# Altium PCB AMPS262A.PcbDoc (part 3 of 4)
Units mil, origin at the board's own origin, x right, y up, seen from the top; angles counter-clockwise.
Board outline 5314.96 x 4803.15 mil, 4 copper layers (Top Layer, GND, Copper Layer 3, Bottom Layer), stack 79.28 mil thick; 324 components, 156 nets, 943 pads, 1411 vias.
Unrouted connection lines stored in the file: 130.
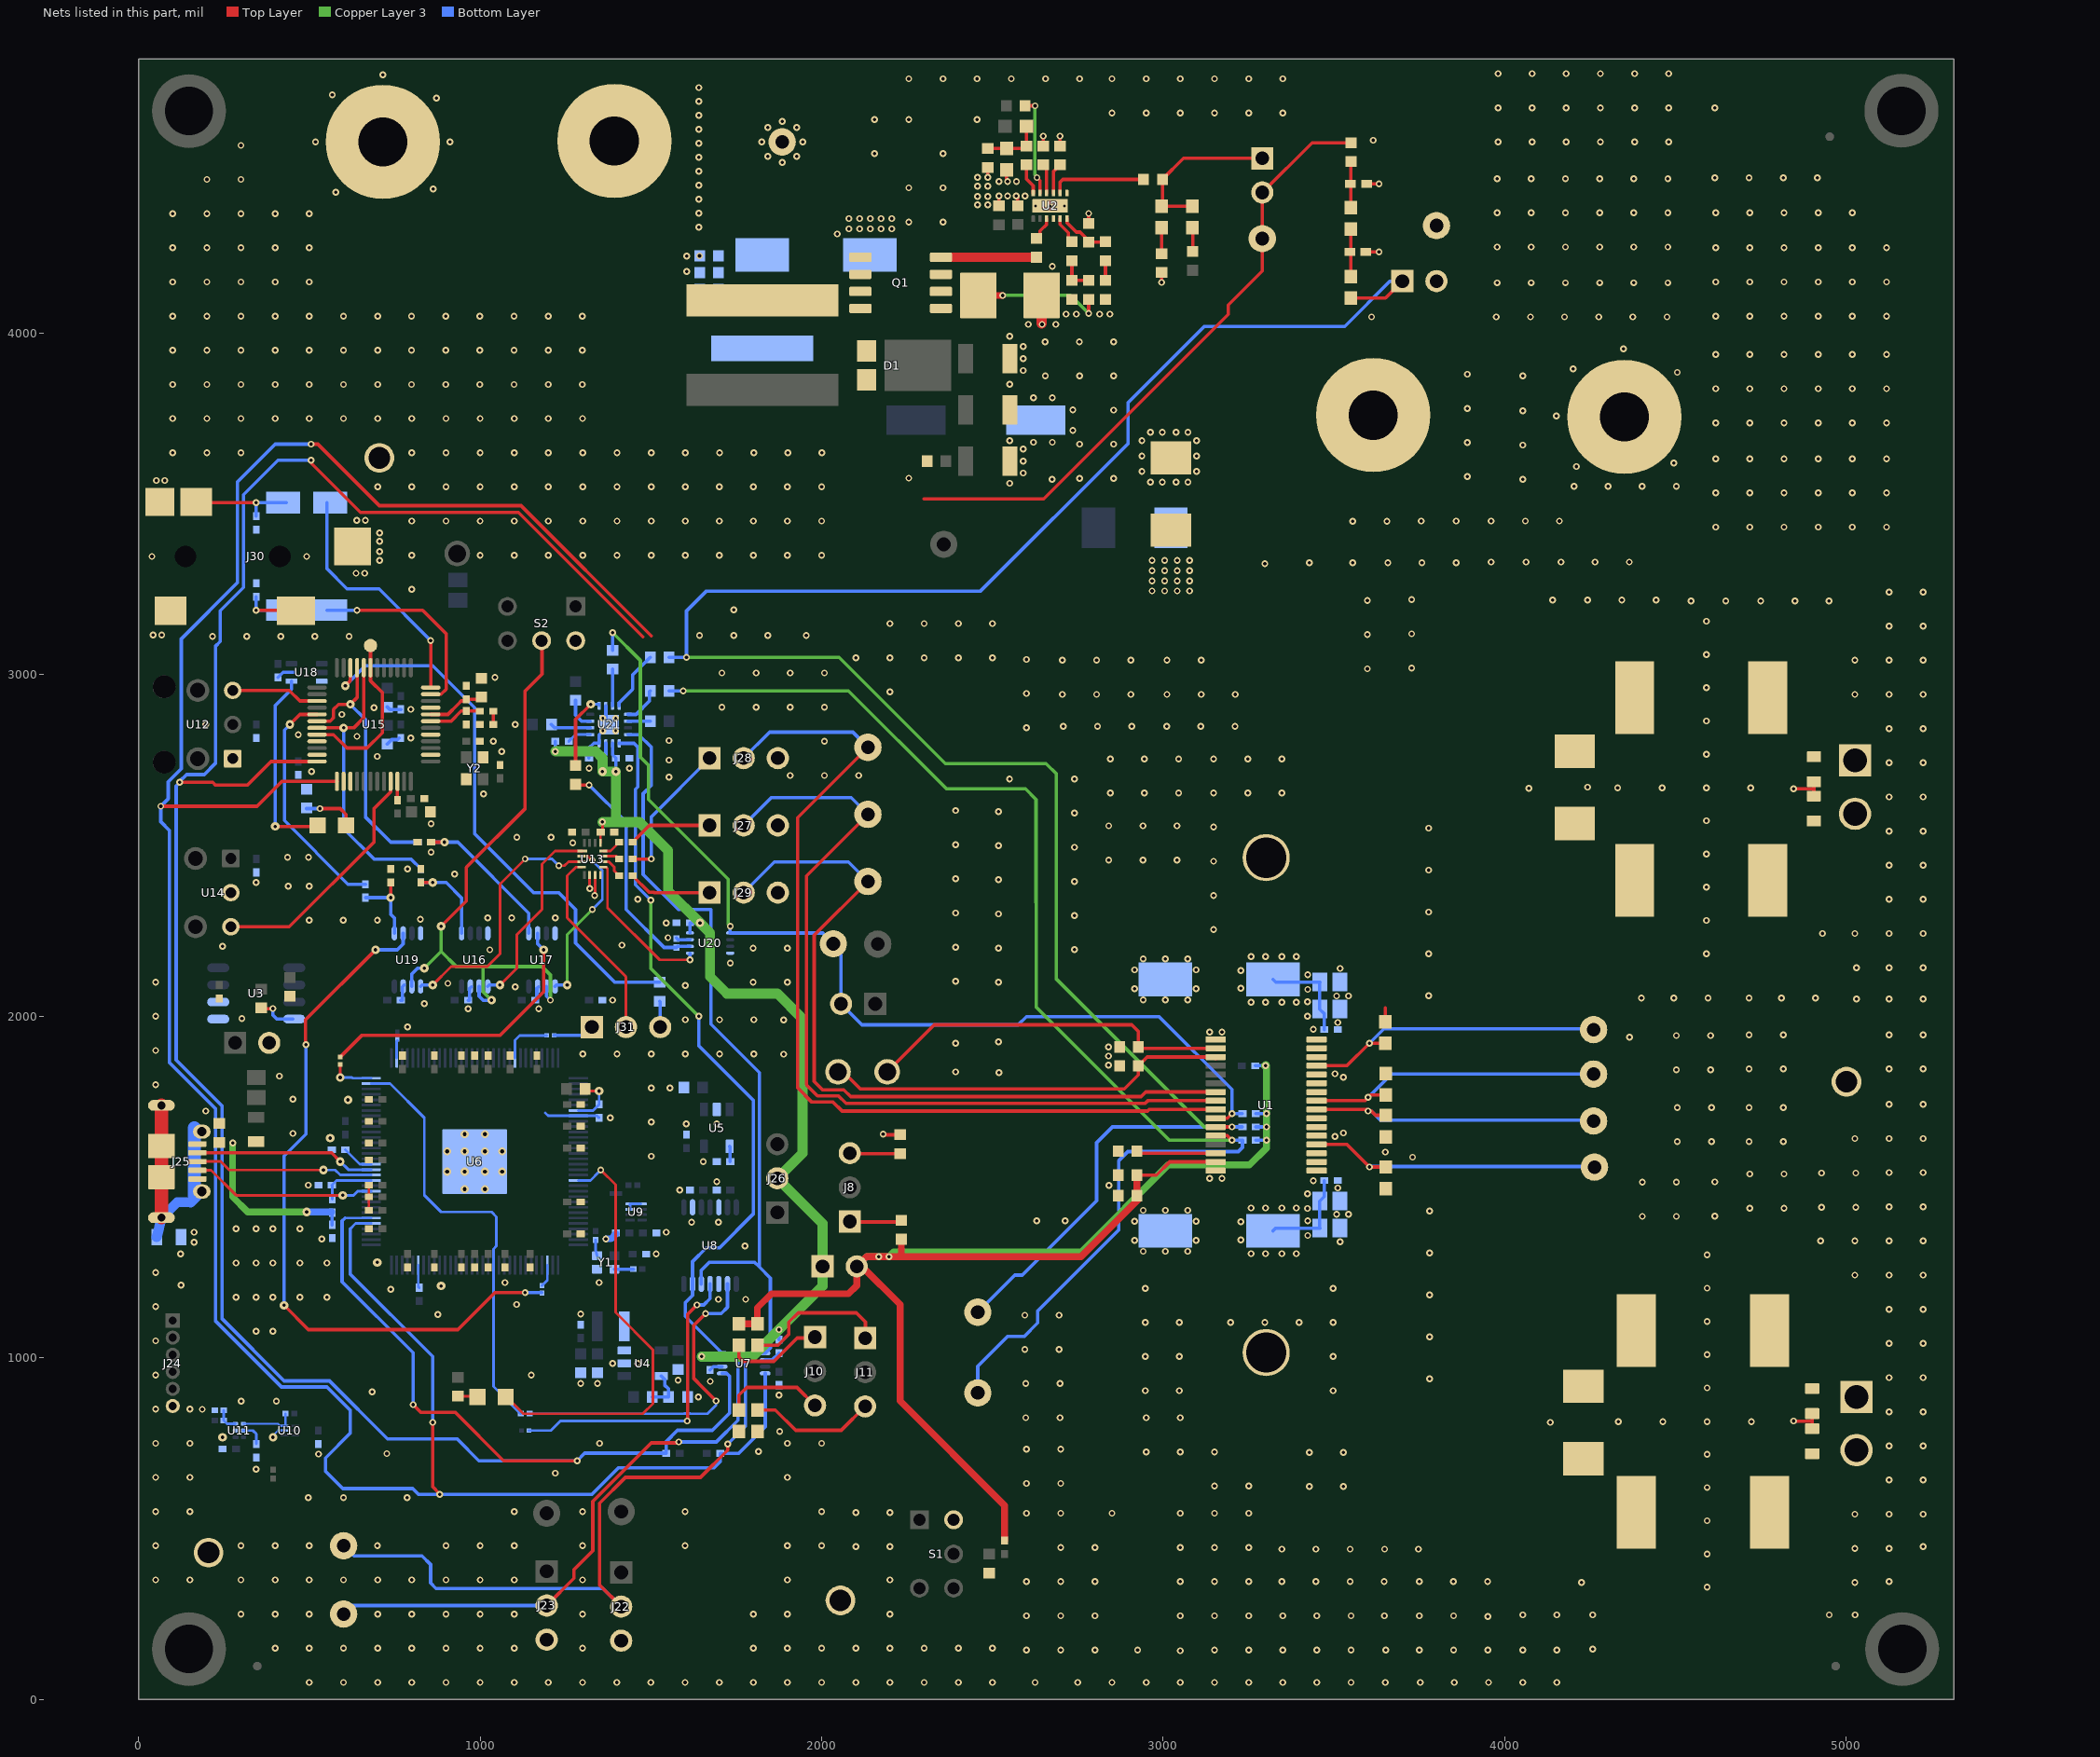
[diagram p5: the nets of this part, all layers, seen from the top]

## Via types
v1: diameter 20, hole 10, Top Layer to Bottom Layer, tented both sides, 1299 vias
v2: diameter 25, hole 10, Top Layer to Bottom Layer, tented both sides, 87 vias
v3: diameter 23.62, hole 11.81, Top Layer to Bottom Layer, 12 vias
v4: diameter 19.68, hole 7.87, Top Layer to Bottom Layer, 7 vias
v5: diameter 20, hole 10, Top Layer to Bottom Layer, 6 vias

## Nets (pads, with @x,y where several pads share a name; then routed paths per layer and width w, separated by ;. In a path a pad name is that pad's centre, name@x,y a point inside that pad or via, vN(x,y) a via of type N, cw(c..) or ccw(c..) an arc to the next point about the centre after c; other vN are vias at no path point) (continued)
BST_A+: C14.1 TP21.1 U1.20 | length 889.5
  Top Layer w9.84: U1.20@3449,1624.97 3537.89,1624.97 v1(3603.86,1559) C14.1@3651.25,1559
  Bottom Layer w10: v1(3603.86,1559) 3605.14,1560.28 4260.75,1560.28 TP21.1@4262.5,1558.52
BST_A-: C16.1 TP22.1 U1.24 | length 881.3
  Top Layer w9.84: 3621.5,1710.36 C16.1@3651.28,1710.36
  Top Layer w10: U1.24@3449,1727.33 3595.17,1727.33 v1(3600,1722.5) 3609.36,1722.5 3621.5,1710.36
  Bottom Layer w10: v1@3600,1722.36 3609.5,1722.36 3635.89,1695.97 4257.56,1695.97 TP22.1@4260,1693.52
BST_B+: C18.1 TP23.1 U1.29 | length 897.2
  Top Layer w9.84: U1.29@3449,1855.29 3537.89,1855.29 v1(3603.61,1921) C18.1@3650,1921
  Bottom Layer w10: v1(3603.61,1921) 3645.97,1963.37 TP23.1@4255,1963.37
BST_B-: C20.1 TP24.1 U1.25 | length 897.7
  Top Layer w10: U1.25@3449,1752.92 3590.42,1752.92 v1(3600,1762.5) 3607.4,1769.9 C20.1@3651.28,1769.9
  Bottom Layer w10: v1(3600,1762.5) 3668.52,1831.02 TP24.1@4260,1831.02
COMP: C38.1 C39.1 U2.6 | length 150.1
  Top Layer w9.84: U2.6@2717.77,4335.49 2717.77,4324.13 2745.78,4296.12 2756.76,4296.12 2781.75,4271.14 C38.1@2781.75,4266.6 C39.1@2829.97,4266.6
CS: R17.1 U2.5 | length 82.2
  Top Layer w9.84: U2.5@2698.08,4335.49 2698.08,4318.76 2722.69,4294.16 2722.69,4277.42 R17.1@2732.53,4267.58
DOUT-XMOS: R47.2 U19.2 | length 2100
  Top Layer w9.84: v2(426,1154) 497.32,1082.68 935.04,1082.68 1043.31,1190.94 v1(1131.89,1190.94) ; v1(490,1917.5) 489.11,1918.39 489.11,1990.09 v2(693.9,2194.88)
  Bottom Layer w9.84: v2(426,1154) 426,1591 490,1655 v1(490,1917.5) ; v2(693.9,2194.88) 757.87,2194.88 774.61,2211.61 U19.2@774.61,2243.11 ; v1(1131.89,1190.94) R47.2@1179.92,1190.94
DVDD1: C11.2 C12.1 J3.2 R1.2 R2.2 R3.2 R4.2 R5.2 R7.2 R8.2 R9.2 U1.15 | length 4439.1
  Top Layer w10: C12.1@2923.28,1535 2980.17,1535 3018.96,1573.79 U1.15@3153.72,1573.79
  Top Layer w20: R8.2@1757.98,1099.99 R9.2@1812.49,1099.99 1811.65,1100.82 1811.65,1146.65 1852.99,1187.99 2078.68,1187.99 2102.69,1212 J3.2@2102.69,1267.97 ; R1.2@2233.15,1347.44 2233.15,1304.15 2225,1296 ; R7.2@2535,465.37 R7.2@2535.5,464.87 2535.5,568 2229.57,873.93 2229.57,1156.43 2118.03,1267.97 J3.2@2102.69,1267.97 ; C11.2@2923.28,1475 C12.1@2923.28,1535 ; C11.2@2926.62,1463.69 2758.93,1296 2225,1296 ; J3.2@2102.69,1267.97 2130.72,1296 v1(2167,1296) v1(2197,1296) 2225,1296
  Copper Layer 3 w20: J3.2@2102.69,1267.97 2130.87,1296.15 v1@2197,1296.15 ; v1(2197,1296) 2211,1310 2455,1310.22 2760,1310.22 3014.7,1564.92 3252.61,1564.92 3301.89,1614.2 v1(3301.89,1637.15) v1(3301.89,1676.15) v1(3301.89,1715.15) v1@3301.89,1853.29
  Copper Layer 3 w25: v1@3299.64,1855.04 v1(3299.89,1855.29) v1@3300.14,1855.54
  Bottom Layer w9.84: R2.2@3271.19,1637.15 v1(3301.89,1637.15) ; R3.2@3271.19,1676.15 v1(3301.89,1676.15) ; R4.2@3271.19,1715.15 v1(3301.89,1715.15)
  Bottom Layer w10: R5.2@3269.19,1855.29 v1(3299.89,1855.29)
FB: R25.1 U2.8 | length 279.3
  Top Layer w9.84: U2.8@2698.08,4410.3 2698.08,4441.79
  Top Layer w10: 2698.08,4441.79 2706.29,4450 R25.1@2942.44,4450
GATE: R15.1 U2.3 | length 68.3
  Top Layer w9.84: R15.1@2629.19,4279.39 2639.03,4289.23 2639.03,4299.08 2658.71,4318.76 U2.3@2658.71,4335.49
GND: C1.1 C2.1 C3.1 C4.2 C5.2 C6.1 C7.1 C8.2 C9.2 C10.1 C11.1 C12.2 C13.1 C15.2 C17.2 C19.2 C21.1 C22.2 C23.2 C24.2 C25.2 C26.2 C27.2 C28.2 C29.2 C30.2 C31.2 C32.2 C33.1 C34.2 C35.2 C36.2 C37.1 C38.2 C40.2 C41.2 C42.1 C43.2 C44.1 C45.1 C46.1 C47.1 C48.1 C49.1 C50.1 C51.1 C52.1 C53.1 C54.1 C55.1 C56.1 C57.1 C58.2 C59.2 C60.2 C61.2 C62.2 C63.1 C64.1 C65.1 C66.1 C67.1 C68.1 C69.1 C70.1 C71.1 C72.1 C73.1 C74.1 C75.1 C76.1 C77.1 C78.1 C79.1 C80.1 C81.1 C82.2 C83.2 C84.1 C85.1 C86.1 C87.1 C88.1 C89.1 C90.1 C91.1 C92.1 C93.2 C94.2 C95.2 C96.2 C97.2 C98.2 C99.2 C100.2 C101.2 C102.2 C103.2 C104.2 C105.2 C106.2 C107.2 C110.2 C111.2 C112.2 C113.2 C114.2 C115.2 C116.2 C117.2 C118.2 C119.2 C120.2 H1.1 H1.2 J13.1 J16.2 J19.2 J20.1 J22.3 J23.3 J24.6 J27.3 J28.3 J29.3 J30.1 J30.4 J30.5 L8.2 R6.1 R10.1 R11.1 R19.1 R20.2 R21.1 R24.1 R30.1 R35.1 R49.1 R58.2 R59.1 R68.1 R69.1 R70.1 R72.1 S1.4 S2.4 TP8.1 TP9.1 TP10.1 TP11.1 TP12.1 U1.1 U1.16 U1.21 U1.22 U1.27 U1.28 U2.4 U2.7 U2.13 U3.1 U3.2 U4.2 U5.2 U6.104 U6.129 U7.2 U8.2 U8.5 U8.10 U9.3 U9.4 U9.5 U10.2 U11.2 U12.1 U13.6 U13.7 U13.8 U14.2 U15.21 U15.23 U15.26 U15.27 U15.38 U15.41 U15.45 U16.4 U16.7 U17.4 U17.7 U18.3 U19.4 U19.7 U20.4 U20.7 U21.6 U21.16 U21.17@1377.95,2854.33 Y1.2 Y2.2 Y2.4 | length 1584.6
  Top Layer w7.87: C69.1@674.21,1432.09 C49.1@674.21,1471.46 C48.1@674.21,1505.91 ; v1(1320.87,2373.8) U13.6@1320.87,2413.39 ; v1(1335.46,2353.5) 1336.61,2354.65 U13.7@1336.61,2413.39
  Top Layer w9.84: v1(2486.31,4456.6) C35.2@2486.31,4485.53 ; C33.1@2519.11,4372.65 v1@2519.11,4401.59 ; v1@2541.31,4448.72 R19.1@2541.31,4477.66 ; C34.2@2574.11,4373.21 v1@2574.11,4402.15 ; R20.2@2648.87,4548.09 v1(2648.87,4577.03) ; C37.1@2698.08,4548.09 v1(2698.08,4577.03) ; C38.2@2781.75,4321.71 v1(2781.75,4350.65) ; v1(2995,4148.5) R30.1@2995,4177.44 ; C41.2@3602.62,4237.61 v1(3631.56,4237.61) ; C40.2@3602.62,4437.61 v1(3631.56,4437.61)
  Top Layer w10: v1(2180,1655.56) 2182.41,1653.15 R6.1@2230,1653.15 ; v1@4842.76,2670.38 v1@4843.37,2669.77 ; v1(4845,815.38) 4845.61,814.77 4900,814.77 ; v1(4845,2666.02) 4905,2666.02 ; C1.1@4900,792.44 4900,814.77 ; C10.1@4900,837.11 4900,814.77 ; C21.1@4905,2644.94 4905,2666.02 ; C13.1@4905,2687.11 4905,2666.02
  Top Layer w30: v1@2643.83,4028.99 R21.1@2643.83,4110.65
  Bottom Layer w5.91: v2@398.62,777.56 408.46,787.4 U10.2@427.17,787.4 U10.2@429.53,787.4
  Bottom Layer w7.87: 1190.94,1717.52 1199.8,1708.66 U6.104@1287.4,1708.66 1342.52,1708.66 C82.2@1348.43,1702.76 ; U9.3@1438.98,1435.04 U9.4@1438.98,1449.8 ; U9.4@1438.98,1450.79 U9.5@1470.47,1450.79
  Bottom Layer w9.84: C104.2@408.46,2992.13 423.23,3006.89 452.76,3006.89 ; C101.2@728.35,2797.24 741.14,2810.04 757.87,2810.04 C100.2@762.8,2814.96 ; C98.2@728.35,2905.51 735.24,2898.62 C99.2@767.72,2898.62 ; C115.2@767.72,2047.24 772.64,2047.24 772.64,2086.61 U19.7@777.56,2091.54 ; C116.2@964.57,2047.24 969.49,2047.24 969.49,2081.69 U16.7@974.41,2086.61 ; C88.1@1161.42,2047.24 1166.34,2047.24 1166.34,2081.69 U17.7@1171.26,2086.61 ; C79.1@1318.9,2755.91 1318.9,2785.43 1333.66,2800.2 1348.43,2800.2 1348.43,2824.8 U21.17@1358.27,2834.65 ; U21.17@1363.19,2869.09 1368.11,2874.02 U21.6@1368.11,2909.45 ; R72.1@1574.8,2229.33 1579.72,2224.41 U20.7@1614.17,2224.41 ; C120.2@1673.23,964.57 1683.07,974.41 U7.2@1708.66,974.41
  Bottom Layer w19.68: v1(1368.11,1348.43) 1382.87,1348.43 C89.1@1397.64,1363.19
  other v1: 500,50 600,50 700,50 800,50 900,50 1000,50 1100,50 1200,50 1300,50 1400,50 1500,50 1600,50 1700,50 1800,50 1900,50 2000,50 2100,50 2200,50 2300,50 2400,50 2500,50 2625,50 2750,50 2850,50 2950,50 3050,50 3150,50 3250,50 3350,50 3450,50 3550,50 3650,50 3752.5,50 3852.5,50 3952.5,50 4052.5,50 4152.5,50 3050,142.64 2600,145 2700,145 2800,145 2925,145 3150,145 3250,145 3350,145 3450,145 3550,145 3651.28,145 3750,145 3850,145 3950,145 4052.5,145 4152.5,145 4257.5,147.64 400,150 500,150 600,150 700,150 800,150 900,150 1000,150 1100,150 1300,150 1800,150 1900,150 2000,150 2100,150 2200,150 2300,150 2400,150 2500,150 3950,242.5 2600,245 2700,245 2800,245 3050,245 3150,245 3250,245 3350,245 3450,245 3550,245 3647.5,245 3750,245 3850,245 4052.5,247.5 4152.5,247.5 4257.5,247.5 4950,247.5 5025.38,247.5 300,250 400,250 500,250 700,250 800,250 900,250 1000,250 1100,250 1300,250 1800,250 1900,250 2200,250 4592.5,328.52 4225,342.36 5025,342.36 2600,345 2700,345 2800,345 3050,345 3150,345 3250,345 3347,345 3447,345 3547,345 3647,345 3749.5,345 3849.5,345 3949.5,345 5125,345 50,350 150,350 300,350 400,350 500,350 600,350 700,350 800,350 900,350 1000,350 1100,350 1300,350 1900,350 2200,350 4592.5,425.83 3347,440 3447,440 3547,440 3648.28,440 3747,440 5025,442.36 5125,442.36 2700,445 2800,445 3050,445 3150,445 3250,445 2100,447.5 2200,447.5 5225,447.5 50,450 300,450 400,450 500,450 699.36,450 900,450 1000,450 1100,450 1300,450 1600,450 1900,450 2000,450 4592.5,523.13 5025,542.36 5125,542.36 5225,542.36 2600,545 2700,545 2850,545 3050,545 3150,545 3250,545 2100,547.5 2200,547.5 50,550 150,550 1100,550 1300,550 1600,550 2000,550 496.65,590.55 600,590.55 785.83,590.55 4592.5,620.43 3427.5,623.58 3527.5,623.58 3150,625 3250,625 2600,632.5 2700,632.5 5125,642.36 5225,642.36 50,650 150,650 1900,650 1220.47,662.5 344.49,674.21 4592.5,717.73 526.57,718.5 727,720 3427.5,723.58 3527.5,723.58 2950,725 3050,725 3150,725 1815,726 2600,732.5 2700,732.5 5125,742.36 5225,742.36 50,750 150,750 1350,750 1900,750 2000,750 1877,785 4132.76,811.02 4332.76,813.52 4462.5,813.52 4592.24,813.52 4721.97,813.52 2597.5,825 2697.5,825 2950,825 3050,825 5125,842.36 5225,842.36 186.64,849.38 50,850 150,850 300.31,873.19 403.65,873.19 1638.78,885.83 1875,890.75 684.06,900.59 2947.5,903.9 3047.5,903.9 3497.5,903.9 4592.5,912.33 1294.29,925.2 1343.5,925.2 2597.5,925 2697.5,925 1673.92,931.33 1579.72,935.04 3780,939 5125,942.36 5225,942.36 50,950 1150,950 1387.8,984.25 1461.61,984.25 2947.5,1003.9 3047.5,1003.9 3497.5,1003.9 4592.5,1009.64 2595,1025 2695,1025 5125,1042.36 5225,1042.36 50,1050 3780,1061.75 344.49,1077.95 393.7,1077.95 2947.5,1103.9 3047.5,1103.9 3197.5,1103.9 3297.5,1103.9 3397.5,1103.9 3497.5,1103.9 4592.5,1106.94 2595,1125 2695,1125 875.98,1126.97 1294.35,1128.3 5125,1142.36 5225,1142.36 50,1150 1107.28,1156.5 1697.83,1171.26 1777.5,1171.26 285.43,1177.95 344.49,1177.95 393.7,1177.95 472.44,1177.95 551.18,1177.95 3780,1184.5 738.19,1200.79 2947.5,1203.9 3497.5,1203.9 4592.5,1204.24 124.04,1213.41 1072.83,1220.47 1348.43,1220.47 5025,1242.36 5125,1242.36 5225,1242.36 50,1250 285.43,1277.95 344.49,1277.95 393.7,1277.95 472.44,1277.95 551.18,1277.95 4592.5,1301.54 123.03,1304.13 1515.75,1304.13 3780,1307.25 2941.46,1312.07 3006.46,1312.07 3071.46,1312.07 1775.17,1327.5 162.4,1338.58 3517.61,1340.02 4925,1342.36 5025,1342.36 5125,1342.36 5225,1342.36 2916.5,1344.36 3096.41,1344.36 536.42,1348.43 162.4,1368.11 1545.28,1368.11 285.43,1377.95 344.49,1377.95 393.7,1377.95 472.44,1377.95 1619.09,1397.64 1697.83,1397.64 2916.5,1399.77 3096.41,1399.77 2630,1401.32 2712.5,1401.32 4402.5,1414.38 4502.5,1414.38 4615,1415.38 3507.5,1420.36 3542.5,1420.36 3780,1430 2941.46,1432.07 3006.46,1432.07 3071.46,1432.07 4717.5,1438.52 4817.5,1438.52 4927.5,1441.02 5027.5,1441.02 5125,1442.36 5225,1442.36 1584.65,1491.14 3510.67,1497.5 2841.42,1505 497.05,1505.91 4402.5,1514.38 4502.5,1514.38 4615,1515.38 1692.91,1515.75 3135.5,1525.9 3171.94,1525.9 4717.5,1538.52 4817.5,1538.52 4927.5,1541.02 5027.5,1541.02 5125,1542.36 5225,1542.36 1653.54,1574.8 3730,1587.5 1501,1590.19 3650,1602.5 4505,1633.15 4605,1633.15 4715,1633.15 4815,1633.15 5025,1642.36 5125,1642.36 5225,1642.36 3502.5,1648.36 451.6,1657.08 3527.5,1658.36 1603.52,1684.88 1692.83,1684.88 1501,1690.19 1381.54,1702.65 196.85,1722.44 4505,1733.15 4605,1733.15 4715,1733.15 4815,1733.15 5125,1742.36 5225,1742.36 451.6,1757.08 1501,1790.19 1555.67,1790.54 50,1800 3527.5,1821.9 412.5,1825 3502.5,1831.9 2519.11,1835 2392.5,1837.5 4502.5,1843.52 4602.5,1843.52 4715,1846.02 4815,1846.02 5125,1846.02 5225,1846.02 2840,1857 2840,1883.5 1889,1889 1301,1890.19 1401,1890.19 1501,1890.19 1601,1890.19 1701,1890.19 1801,1890.19 50,1900 2840,1910 2392.5,1921 2517.5,1925 4364.98,1939.37 4502.5,1943.52 4602.5,1943.52 4715,1946.02 4815,1946.02 5125,1946.02 5225,1946.02 3135.5,1954.36 3171.94,1954.36 787.4,1968.5 3510.67,1982.07 1889,1989 1601,1990.19 1701,1990.19 1801,1990.19 302.5,1993.11 50,2000 965.2,2022.26 1171.89,2021.83 836.61,2037.4 1387.8,2047.24 2941.46,2048.19 3006.46,2048.19 3071.46,2048.19 5030,2051.02 5125,2051.02 5225,2051.02 4400,2053.52 4495,2053.52 4595,2053.52 4715,2053.52 4810,2053.52 4910,2053.52 3507.5,2059.9 3542.5,2059.9 3777.5,2060 2916.5,2080.48 3096.41,2080.48 1102.36,2086.61 1601,2090.19 905.51,2096.46 50,2100 1799.19,2099.66 1899.19,2099.66 2517.5,2099.66 2392.5,2102.5 2916.5,2135.9 3096.41,2135.9 3517.61,2140.24 5030,2142.36 5125,2142.36 5225,2142.36 1732.28,2155.51 2941.46,2168.19 3006.46,2168.19 3071.46,2168.19 3777.5,2182.75 4590.26,2183.52 1028.54,2194.88 2740,2195 1799.19,2199.66 1899.19,2199.66 2517.5,2199.66 2392.5,2202.5 246.06,2204.72 1414.86,2208.5 1549.87,2230.22 4930,2242.36 5025,2242.36 5125,2242.36 5225,2242.36 3147.5,2253.9 1545.28,2273.62 499.36,2281.4 599.36,2281.4 699.36,2281.4 4590.26,2280.83 824.96,2284.42 1022.13,2287.91 1092.52,2288.39 1220.47,2288.39 2740,2295 2517.5,2299.66 2392.5,2302.5 3777.5,2305.5 5125,2342.36 5225,2342.36 1461.61,2342.52 3147.5,2353.9 4590.26,2378.13 438.02,2381.4 499.36,2381.4 344.49,2391.73 2740,2395 2517.5,2399.66 2392.5,2402.5 925.2,2416.34 3777.5,2428.25 787.4,2431.1 5125,2442.36 5225,2442.36 3147.5,2453.9 2840.6,2457.5 2940.6,2457.5 3040.6,2457.5 436.3,2466.01 497.64,2466.01 4590.26,2475.43 856.3,2480.32 2740,2495 2517.5,2499.66 2392.5,2502.5 1271.18,2508.18 1107.76,2524 1207.76,2524 5125,2542.36 5225,2542.36 3777.5,2551 3147.5,2553.9 2840.6,2557.5 2940.6,2557.5 3040.6,2557.5 856.3,2563.98 4590.26,2572.73 2740,2595 2517.5,2599.66 2392.5,2602.5 5125,2642.36 5225,2642.36 1010,2651 2845,2653.9 2945,2653.9 3045,2653.9 3147.5,2653.9 3247.5,2653.9 3347.5,2653.9 4070,2667.5 4330.53,2668.52 4460.26,2668.52 4590,2668.52 4719.74,2668.52 4242.5,2671.02 2550,2695 2740,2695 1553.15,2700 1908.03,2705.07 2008.03,2705.07 2108.03,2705.07 506.89,2716.54 1318.9,2726.38 1437.01,2726.38 5125,2742.36 5225,2742.36 1553.15,2750 2845,2753.9 2945,2753.9 3045,2753.9 3147.5,2753.9 3247.5,2753.9 3347.5,2753.9 698.82,2760.83 4590.26,2767.33 1062.99,2775.59 1038.39,2805.12 2008.03,2805.07 1553.15,2807.5 797.24,2814.96 639.76,2819.88 467.52,2824.8 5125,2842.36 5225,2842.36 2600,2845 2707.5,2849.33 2807.5,2849.33 2907.5,2849.33 3010,2849.33 3110,2849.33 3210,2849.33 196.85,2854.33 1102.36,2854.33 4590.26,2864.64 595.47,2883.86 797.24,2898.62 688.98,2903.54 1708.03,2905.07 1808.03,2905.07 1908.03,2905.07 2008.03,2905.07 2705,2942.5 2805,2942.5 2905,2942.5 3010.88,2942.5 3110.88,2942.5 3210.88,2942.5 5025,2942.36 5125,2942.36 5225,2942.36 2600,2945 2200,2950 4590.26,2961.94 1043.31,2992.13 1708.03,3005.07 1808.03,3005.07 1908.03,3005.07 2008.03,3005.07 3597.5,3017.5 3727.5,3020 2705,3042.5 2805,3042.5 2905,3042.5 3010.88,3042.5 3110.88,3042.5 5025,3042.36 5125,3042.36 5225,3042.36 2600,3045 2100,3050 2200,3050 2300,3050 2400,3050 2500,3050 4590.26,3059.24 216.47,3112.46 316.47,3112.46 416.47,3112.46 516.47,3112.46 616.47,3112.46 1642.61,3115 1742.61,3115 1842.61,3115 1955,3115 42.84,3116.73 67.84,3116.73 3597.5,3117.5 3727.5,3120 5125,3142.36 5225,3142.36 2200,3150 2300,3150 2400,3150 2500,3150 4590.26,3156.54 1742.61,3190 4545,3216.02 4646.91,3216.02 4749.41,3216.02 4849.41,3216.02 4949.41,3216.02 3597.5,3217.5 4140,3218.52 4242.5,3218.52 4342.5,3218.52 4442.5,3218.52 3727.5,3220 5125,3242.36 5225,3242.36 800,3250 637.02,3297.13 662.02,3297.13 3297.5,3325 3427.5,3327.5 3555,3327.5 3657.5,3327.5 3757.5,3327.5 3857.5,3327.5 3960,3330 4061.91,3330 4164.41,3330 4264.41,3330 4364.41,3330 705.49,3334.55 39.37,3346.46 492.13,3346.46 800,3350 1000,3350 1100,3350 1200,3350 1301,3350 1401,3350 1501,3350 1601,3350 1700,3350 1800,3350 1900,3350 2000,3350 705.49,3360.49 705.49,3390.49 705.49,3415.49 4617.5,3432.5 4717.5,3432.5 4817.5,3432.5 4917.5,3432.5 5017.5,3432.5 5117.5,3432.5 3554.83,3449.35 3654.83,3449.35 800,3450 900,3450 1000,3450 1100,3450 1200,3450 1301,3450 1401,3450 1501,3450 1601,3450 1700,3450 1800,3450 1900,3450 2000,3450 3755.59,3450.12 3857.5,3450.12 3960,3450.12 4060,3450.12 4160,3450.12 639.25,3452.2 664.25,3452.2 4617.5,3532.5 4717.5,3532.5 4817.5,3532.5 4917.5,3532.5 5017.5,3532.5 5117.5,3532.5 700,3550 800,3550 900,3550 1000,3550 1100,3550 1200,3550 1301,3550 1401,3550 1501,3550 1601,3550 1700,3550 1800,3550 1900,3550 2000,3550 4202.36,3551.9 4302.36,3551.9 4402.36,3551.9 4502.36,3551.9 2550.17,3560.65 51.86,3568.86 76.86,3568.86 2675,3572.5 4052.5,3572.5 2755,3575 2855,3575 2255.17,3575.65 3890,3580 2590.17,3590.65 4209.57,3609.86 4495,3619.71 2590.17,3625.65 4617.5,3632.5 4717.5,3632.5 4817.5,3632.5 4917.5,3632.5 5017.5,3632.5 5117.5,3632.5 100,3650 200,3650 300,3650 800,3650 900,3650 1000,3650 1100,3650 1200,3650 1301,3650 1401,3650 1501,3650 1601,3650 1701,3650 1801,3650 1901,3650 2001,3650 2590.17,3660.65 4052.5,3672.5 2755,3675 2855,3675 3890,3680 2620.17,3680.65 2675.17,3680.65 2550.17,3685.65 2735.17,3715.65 4617.5,3737.5 4717.5,3737.5 4817.5,3737.5 4917.5,3737.5 5017.5,3737.5 5117.5,3737.5 100,3750 200,3750 300,3750 400,3750 500,3750 600,3750 700,3750 800,3750 900,3750 1000,3750 1100,3750 1200,3750 1300,3750 4150.51,3757.5 4052.5,3772.5 2855,3775 2735.17,3775.65 3890,3780 2620.17,3810.65 2675.17,3810.65 4617.5,3837.5 4717.5,3837.5 4817.5,3837.5 4917.5,3837.5 5017.5,3837.5 5117.5,3837.5 100,3850 200,3850 300,3850 400,3850 500,3850 600,3850 700,3850 799.21,3850 899.21,3850 999.21,3850 1099.21,3850 1199.21,3850 1299.21,3850 2550.17,3850.65 2655,3875 2755,3875 2855,3875 4052.5,3875 3890,3880 4504.84,3885.45 2590.17,3890.65 4199.72,3895.3 2590.17,3925.65 4617.5,3937.5 4717.5,3937.5 4817.5,3937.5 4917.5,3937.5 5017.5,3937.5 5117.5,3937.5 100,3950 200,3950 300,3950 400,3950 500,3950 600,3950 700,3950 799.21,3950 899.21,3950 999.21,3950 1099.21,3950 1199.21,3950 1299.21,3950 4347.36,3954.35 2590.17,3960.65 2654.32,3974.69 2754.32,3974.69 2854.32,3974.69 2550.17,3990.65 2605.17,4025.65 2645.17,4025.65 2685.17,4025.65 3610,4047.5 3975,4047.5 4075,4047.5 4175,4047.5 4275,4047.5 4375,4047.5 4475,4047.5 100,4050 200,4050 300,4050 400,4050 500,4050 600,4050 700,4050 799.21,4050 899.21,4050 999.21,4050 1099.21,4050 1199.21,4050 1299.21,4050 4617.5,4050 4717.5,4050 4817.5,4050 4917.5,4050 5017.5,4050 5117.5,4050 2715.17,4055.65 2745.17,4055.65 2813.6,4055.65 2843.6,4055.65 3977.5,4147.5 4077.5,4147.5 4177.5,4147.5 4277.5,4147.5 4377.5,4147.5 4477.5,4147.5 100,4150 200,4150 300,4150 400,4150 500,4150 4617.5,4150 4717.5,4150 4817.5,4150 4917.5,4150 5017.5,4150 5117.5,4150 1605.17,4180.65 2675.17,4195.65 1605.17,4225.65 1642.61,4226.28 100,4250 200,4250 300,4250 400,4250 500,4250 4617.5,4250 4717.5,4250 4817.5,4250 4917.5,4250 5017.5,4250 5117.5,4250 3977.5,4252.5 4077.5,4252.5 4177.5,4252.5 4277.5,4252.5 4377.5,4252.5 4477.5,4252.5 2045.17,4290.65 2080.17,4305.65 2111.42,4305.65 2142.67,4305.65 2173.92,4305.65 2205.17,4305.65 2255.17,4325.65 2355.17,4325.65 2080.17,4335.65 2111.42,4335.65 2142.67,4335.65 2173.92,4335.65 2205.17,4335.65 100,4350 200,4350 300,4350 400,4350 500,4350 3977.5,4352.5 4077.5,4352.5 4177.5,4352.5 4277.5,4352.5 4377.5,4352.5 4477.5,4352.5 4617.5,4352.5 4717.5,4352.5 4817.5,4352.5 4917.5,4352.5 5017.5,4352.5 2456.31,4375.65 2486.31,4375.65 2456.31,4400.65 2486.31,4400.65 2519.11,4402.15 2544.46,4402.15 2569.82,4402.15 2595.17,4402.15 577.2,4412.36 862.64,4422.2 2255.17,4425.65 2355.17,4425.65 2456.31,4430.65 2486.31,4430.65 2519.11,4443.72 2544.46,4443.72 2570.17,4443.72 200,4450 300,4450 3977.5,4452.5 4077.5,4452.5 4177.5,4452.5 4277.5,4452.5 4377.5,4452.5 4477.5,4452.5 4615,4455 4715,4455 4815,4455 4915,4455 2456.31,4456.6 2155.17,4525.65 2355.17,4525.65 300,4550 518.15,4560 911.85,4560 3980,4560 4080,4560 4180,4560 4280,4560 4380,4560 4480,4560 3615,4565 2155.17,4625.65 2255.17,4625.65 2455.17,4625.65 2850,4645 2950,4645 3050,4645 3150,4645 3250,4645 3350,4645 3980,4660 4080,4660 4180,4660 4280,4660 4380,4660 4480,4660 4615,4660 872.48,4687.95 567.36,4697.8 2255.17,4745 2355.17,4745 2455.17,4745 2555.17,4745 2655.17,4745 2755.17,4745 2850,4745 2950,4745 3050,4745 3150,4745 3250,4745 3350,4745 715,4756.85 3980,4760 4080,4760 4180,4760 4280,4760 4380,4760 4480,4760
  other v2: 246.06,767.72 393.7,767.72 885.83,1210.63 698.82,1279.53 561.02,1643.7 613.22,1755.61
  other v3: 954.72,1494.09 1013.78,1494.09 903.54,1545.28 954.72,1545.28 1013.78,1545.28 1064.96,1545.28 903.54,1604.33 954.72,1604.33 1013.78,1604.33 1064.96,1604.33 954.72,1655.51 1013.78,1655.51
  other v4: 1359.25,2835.63 1396.65,2835.63 1359.25,2873.03 1396.65,2873.03 2626.23,4372.9 2668.56,4372.9 2710.88,4372.9
GND-USB: J25.5 J25.6 J25.7 J25.8 J25.9 J25.10 J25.11 L8.1 | length 736.7
  Top Layer w39.37: J25.7@67.09,1410.43 J25.8@67.09,1529.53 J25.9@67.09,1620.08 J25.10@67.09,1739.17
  Bottom Layer w29.53: L8.1@53.15,1353.35 J25.7@67.09,1410.43 113.58,1455.86 152.65,1455.4 J25.6@185.2,1487.2 ; J25.7@87.76,1410.19 J25.7@87.8,1412.96
  Bottom Layer w39.37: J25.6@163.39,1476.38 J25.11@163.39,1673.23
GPIO0_F\A\U\L\T\: R2.1 R78.2 TP1.1 U1.12 | length 3910.5
  Top Layer w9.84: U1.12@3153.72,1650.56 3187.7,1650.56 v1(3201.11,1637.15)
  Copper Layer 3 w9.84: v1(1594.49,2952.76) 2078.65,2952.76 2365.38,2666.02 2596.48,2666.02 2627.5,2635 2628.26,2026.74 3017.85,1637.15 v1(3201.11,1637.15)
  Bottom Layer w9.84: R78.2@1553.15,2952.76 v1(1594.49,2952.76) ; v1(3201.11,1637.15) R2.1@3231.82,1637.15
  Bottom Layer w10: TP1.1@2457.11,897.5 2457.11,975.89 2543.72,1062.5 2592.5,1062.5 2632.5,1102.5 2632.5,1137.5 2870.17,1375.17 2870.17,1577.76 2896.3,1603.9 3219.5,1603.9 3231.82,1616.21 R2.1@3231.82,1637.15
GPIO1_Hybrid_Pro: J16.1 R3.1 R28.2 R77.2 TP2.1 U1.11 | length 6588.3
  Top Layer w9.84: U1.11@3153.72,1676.15 v1(3201.11,1676.15) ; R28.2@3549.5,4103.12 3650.62,4103.12 J16.1@3700,4152.5
  Copper Layer 3 w9.84: v1(1604.33,3051.18) 2050.72,3051.18
  Copper Layer 3 w10: 2050.72,3051.18 2361.9,2740 2656.9,2740 2687.35,2709.54 2687.35,2108.79 3119.99,1676.15 v1(3201.11,1676.15)
  Bottom Layer w9.84: R77.2@1553.15,3051.18 v1(1604.33,3051.18) 1604.33,3186.83 1662.66,3245.16 2465.16,3245.16 2897.5,3677.5 2897.5,3797.5 3120,4020 3531.36,4020 3663.86,4152.5 J16.1@3700,4152.5 ; v1(3201.11,1676.15) R3.1@3231.82,1676.15
  Bottom Layer w10: TP2.1@2457.11,1133.9 2565.72,1242.5 2587.5,1242.5 2805,1460 2805,1630 2851.15,1676.15 v1(3201.11,1676.15)
GPIO2_W\A\R\N\: J9.2 R4.1 R76.2 TP3.1 U1.10 U20.1 | length 2995.8
  Top Layer w10: U1.10@3153.72,1701.74 3187.7,1701.74 v1(3201.11,1715.15)
  Copper Layer 3 w10: v1(1387.8,3123.03) 1469,3041.83 1469,2759 1493,2735 1493,2635 1726.3,2401.7 1726.3,2269.76 v1(1732.28,2263.78)
  Bottom Layer w9.84: R76.2@1387.8,3071.85 v1(1387.8,3123.03) ; U20.1@1732.28,2244.09 v1(1732.28,2263.78) ; v1(3201.11,1715.15) R4.1@3231.82,1715.15
  Bottom Layer w10: U20.1@1732.28,2244.09 2002.6,2244.09 TP3.1@2034.2,2212.5 2034.2,2201.88 2056.62,2179.46 J9.2@2056.62,2036.56 2118.18,1975 2575,1975 2599.27,1999.27 2987.67,1999.27 3201.11,1785.83 v1(3201.11,1715.15)
I2S-MUX_CTRL: S2.5 U16.6 U17.6 U19.6 | length 1827.3
  Top Layer w9.84: v2(885.83,2263.78) 959.65,2337.6 959.65,2436.02 1131.89,2608.27 1131.89,2952.76 1181.1,3001.97 S2.5@1181.1,3099.61
  Copper Layer 3 w9.84: v2(836.61,2140.75) 885.83,2189.96 ; v2(885.83,2263.78) 885.83,2189.96 ; v2(1033.46,2047.24) 1008.86,2071.85 1008.86,2145.67 ; v1(1205.71,2047.24) 1205.71,2121.06 1181.1,2145.67 1008.86,2145.67 ; 885.83,2189.96 930.12,2145.67 1008.86,2145.67
  Bottom Layer w9.84: U19.6@800.2,2087.6 800.2,2124.02 816.93,2140.75 v2(836.61,2140.75) ; U16.6@997.05,2087.6 997.05,2059.06 1008.86,2047.24 v2(1033.46,2047.24) ; U17.6@1193.9,2087.6 1193.9,2059.06 v1(1205.71,2047.24)
IOVDD: C79.2 C80.2 C118.1 C119.1 C120.1 J3.1 J26.2 R39.2 R79.2 U7.3 U13.13 U20.8 U21.14 U21.15 | length 3067.6
  Top Layer w7.87: U13.13@1352.36,2507.87 1352.36,2538.39 C119.1@1353.35,2539.37 1358.27,2544.29 v1(1358.27,2568.9)
  Copper Layer 3 w29.53: v1(1220.47,2775.59) 1338.58,2775.59 1358.27,2755.91 v2(1358.27,2716.54) v2(1397.64,2716.54) 1397.64,2568.9 ; v1(1358.27,2568.9) 1397.64,2568.9 ; v1(1648.62,1003.94) 1796.26,1003.94 v1(1875,1082.68) 2002.69,1210.37 J3.1@2002.69,1267.97 2002.69,1392.98 J26.2@1870.08,1525.59 1943.9,1599.41 1943.9,1727 1943.9,1993.11 1870.08,2066.93 1722.44,2066.93 1673.23,2116.14 1673.23,2244.09 v2(1643.7,2273.62) 1550.2,2367.13 1550.2,2485.24 1466.54,2568.9 1397.64,2568.9
  Bottom Layer w9.84: v1(1220.47,2775.59) R79.2@1220.47,2805.12 ; v2(1358.27,2716.54) C79.2@1358.27,2755.91 1368.11,2765.75 U21.15@1368.11,2799.21 ; U21.14@1387.8,2799.21 1387.8,2765.75 C80.2@1397.64,2755.91 v2(1397.64,2716.54) ; U20.8@1614.17,2244.09 C118.1@1614.17,2273.62 v2(1643.7,2273.62) ; C120.1@1673.23,1003.94 1683.07,994.09 U7.3@1708.66,994.09 ; R39.2@1875,1053.15 v1(1875,1082.68)
  Bottom Layer w19.68: v1(1648.62,1003.94) C120.1@1673.23,1003.94
Left+: C1.2 J2.2 L1.2
Left-: C10.2 J2.1 L2.2
LRCLK: J28.2 TP17.1 U1.9 | length 2750.6
  Top Layer w9.84: 1970,1750 1929.27,1790.73 1929.27,2581.44 TP17.1@2135.5,2787.67
  Top Layer w10: 1970,1749.41 2032.89,1749.41 2059.86,1722.44 2954.4,1722.44 2959.29,1727.33 U1.9@3153.72,1727.33
  Bottom Layer w10: J28.2@1771.65,2755.91 1847.75,2832 2091.17,2832 TP17.1@2135.5,2787.67
LRCLK-MUX: J28.1 R62.2 | length 420.8
  Top Layer w9.84: R62.2@1446.85,2460.63 v1(1500.98,2460.63)
  Bottom Layer w9.84: v1(1500.98,2460.63) 1500.98,2583.66 J28.1@1673.23,2755.91
LRCLK-SPDIF: C103.1 R65.2 U17.1 | length 470.9
  Top Layer w9.84: C103.1@856.3,2509.84 v2(895.67,2509.84)
  Bottom Layer w9.84: R65.2@856.3,2509.84 935.04,2509.84 1142.72,2302.17 U17.1@1142.72,2243.11
LRCLK-XMOS: R42.2 U17.2 | length 853.1
  Top Layer w9.84: R42.2@590.55,1881.1 653.35,1943.9 1058.07,1943.9 1186.02,2071.85 v2(1186.02,2194.88)
  Bottom Layer w9.84: U17.2@1168.31,2243.11 1168.31,2212.6 v2(1186.02,2194.88)
MCLK-XMOS: R53.1 U6.13 U6.63 | length 1273.9
  Bottom Layer w7.87: U6.63@681.1,1803.15 736.46,1803.15 836.61,1703 836.61,1476.38 885.83,1427.17 1033.46,1427.17 1047.93,1412.7 1047.93,1327.48 1039.37,1318.91 U6.13@1039.37,1271.65 1039.37,916.14 R53.1@1118.9,836.61
NetC15_1: C15.1 U1.14 | length 227
  Top Layer w10: C15.1@2927.97,1596.39 2930.95,1599.38 U1.14@3153.72,1599.38
NetC17_1: C17.1 J5.1 U1.2 | length 1074
  Top Layer w10: J5.1@2191.86,1837.54 2329.32,1975 2908,1975 2927.22,1955.78 C17.1@2927.22,1910 2930.75,1906.47 U1.2@3153.72,1906.47
NetC19_1: C19.1 J4.1 U1.3 | length 1181.9
  Top Layer w10: J4.1@2047.86,1837.54 2062.46,1837.54 2097.13,1802.87 2097.4,1802.87 2113.11,1787.17 2886.17,1787.17 2927.22,1828.22 C19.1@2927.22,1855.24 2952.86,1880.88 U1.3@3153.72,1880.88
  Top Layer w17: U1.3@3153.36,1880.52 U1.3@3153.72,1880.88
NetC35_1: C35.1 R13.1 R14.1 R19.2 | length 174
  Top Layer w9.84: C35.1@2486.31,4540.65 R19.2@2541.31,4540.65 2592.22,4540.65 R14.1@2599.66,4548.09 R13.1@2599.66,4605.65
NetC36_1: C36.1 R17.2 R18.1 | length 107.3
  Top Layer w9.84: R17.2@2732.53,4212.46 C36.1@2732.53,4154.39 R18.1@2781.75,4154.39
NetC39_2: C39.2 R24.2 | length 58.1
  Top Layer w9.84: R24.2@2830.96,4154.39 C39.2@2830.96,4212.46
NetC40_1: C40.1 R26.2 R27.1 | length 135
  Top Layer w10: R27.1@3549.39,4368.11 R26.2@3549.39,4503.12
NetC41_1: C41.1 R27.2 R28.1 | length 139.1
  Top Layer w10: R27.2@3549.39,4305.12 3549.5,4305.01 R28.1@3549.5,4166.11
NetC64_2: C64.2 U5.4 | length 45.1
  Bottom Layer w9.84: U5.4@1730.31,1619.09 1732.28,1617.13 C64.2@1732.28,1574.8
NetC82_1: C82.1 R40.2 U6.103 | length 149.1
  Top Layer w7.87: R40.2@1307.09,1781.5 v2(1348.43,1781.5)
  Bottom Layer w7.87: U6.103@1287.4,1724.41 1330.71,1724.41 C82.1@1348.43,1742.13 v2(1348.43,1781.5)
NetC84_2: C84.2 U11.5 | length 142
  Bottom Layer w7.87: 334.65,787.4 344.49,777.56 ; 334.65,787.4 U11.5@307.09,787.4 334.65,787.4 ; 334.65,787.4 344.49,777.56 ; 344.49,777.56 C84.2@344.49,748.03 344.49,777.56
NetC108_2: C108.2 J30.2 R70.2 | length 301.7
  Top Layer w9.84: J30.2@170.74,3503.94 v1(344.49,3503.94)
  Bottom Layer w9.84: R70.2@344.49,3464.57 v1(344.49,3503.94) C108.2@433.07,3503.94
NetC109_2: C109.2 J30.3 R69.2 | length 242.2
  Top Layer w9.84: v1(344.49,3188.98) J30.3@458.7,3188.98
  Bottom Layer w9.84: R69.2@344.49,3228.35 v1(344.49,3188.98) C109.2@433.07,3188.98
NetC110_1: C110.1 C111.1 U15.44 | length 171
  Top Layer w9.84: U15.44@855.32,2883.86 905.51,2883.86 935.04,2913.39 944.88,2923.23 954.72,2923.23 C111.1@959.65,2928.15 999.02,2928.15 999.02,2930.12 C110.1@1003.94,2935.04
NetC112_1: C112.1 R71.1 U15.43 | length 155.9
  Top Layer w9.84: U15.43@855.32,2864.17 915.35,2864.17 944.88,2893.7 C112.1@959.65,2893.7 R71.1@999.02,2893.7
NetC113_1: C113.1 R71.2 | length 39.4
  Top Layer w9.84: C113.1@1038.39,2854.33 R71.2@1038.39,2893.7
NetD2_1: D2.1 R45.1 | length 55.1
  Top Layer w7.87: R45.1@935.04,887.8 D2.1@990.16,887.8
NetD2_2: D2.2 U6.116 | length 1288
  Top Layer w7.87: D2.2@1077.76,885.83 1126.97,836.61 1476.38,836.61 1505.91,866.14 1505.91,1023.62 1396.65,1132.87 1396.65,1506.89 v1(1353.35,1550.2)
  Bottom Layer w7.87: U6.116@1287.4,1519.68 1322.83,1519.68 1348.43,1545.28 v1@1348.43,1550.2 ; v1@1350.89,1547.74 v1(1353.35,1550.2)
NetD3_1: D3.1 U18.4 | length 571
  Top Layer w9.84: v2(400,2556) 521.55,2556 D3.1@524.61,2559.06
  Bottom Layer w9.84: v2(400,2556) 400,2909.84 447.83,2957.68 U18.4@447.83,2981.3
NetD3_2: D3.2 R68.2 | length 154.6
  Top Layer w9.84: v1(531.5,2608.27) 590.55,2608.27 607.28,2591.54 D3.2@607.28,2559.06
  Bottom Layer w9.84: R68.2@492.13,2608.27 v1(531.5,2608.27)
NetJ8_1: J8.1 R1.1 | length 153
  Top Layer w10: J8.1@2082.31,1399.37 2083.63,1398.05 R1.1@2234.82,1398.05
NetJ8_3: J8.3 R6.2 | length 148.6
  Top Layer w10: J8.3@2082.31,1599.37 2082.14,1599.19 2083.29,1598.03 R6.2@2230,1598.03
NetJ10_1: J10.1 R8.1 | length 291.8
  Top Layer w10: R8.1@1757.98,1037 1757.98,1002.02 1770,990 1860,990 1928,1058 1977.46,1058 J10.1@1980.41,1060.95
NetJ10_3: J10.3 R10.2 | length 297.1
  Top Layer w10: R10.2@1758,847.52 1758,891 1780.62,913.62 1927.73,913.62 J10.3@1980.41,860.95
NetJ11_1: J11.1 R9.1 | length 434.7
  Top Layer w10: R9.1@1812.49,1037 1872,1037 1904,1069 1904,1105 1931,1132 2101.43,1132 2128,1105.43 2128,1058.54 J11.1@2127.41,1057.95
NetJ11_3: J11.3 R11.2 | length 368.6
  Top Layer w10: R11.2@1812.47,847.52 1864.48,847.52 1924,788 2057.46,788 J11.3@2127.41,857.95
NetJ15_1: J15.1 R23.1 R25.2 R29.2 | length 520.8
  Top Layer w9.84: J15.1@3290,4511.95 J15.1@3313.44,4535.39
  Top Layer w10: R23.1@3085,4371.5 R29.2@2995,4371.5 2997.56,4374.06 R25.2@2997.56,4450 3059.51,4511.95 J15.1@3290,4511.95
NetJ15_2: J15.2 R26.1 TP7.1 | length 1832.4
  Top Layer w9.84: 2300,3515 2650,3515 3190,4055 3190,4082.31 3290,4182.31 TP7.1@3290,4276.95 ; J15.2@3290,4411.95 3435.61,4557.56 R26.1@3550,4557.56
  Top Layer w10: TP7.1@3290,4276.95 J15.2@3290,4411.95
NetR22_1: R22.1 R23.2 | length 65.5
  Top Layer w9.84: R22.1@3086.32,4239.21 R23.2@3086.32,4304.66
NetR29_1: R29.1 R30.2 | length 75.9
  Top Layer w10: R30.2@2995,4232.56 R29.1@2995,4308.5
NetR32_1: R32.1 U3.8 | length 117.6
  Top Layer w9.84: R32.1@359.25,2024.61 361.22,2022.64 v1(393.7,2022.64)
  Bottom Layer w9.84: v1(393.7,2022.64) 393.7,2002.95 404.72,1991.93 U3.8@451.77,1991.93
NetR34_1: R34.1 R35.2 U4.5 | length 118.2
  Bottom Layer w9.84: R34.1@1503.94,885.83 R35.2@1552.17,885.83 1552.17,908.46 1540.35,920.28 1540.35,937.01 U4.5@1530.51,946.85
NetR36_2: R36.2 U6.27 | length 134.3
  Bottom Layer w7.87: R36.2@818.9,1208.66 R36.2@821.85,1205.71 R36.2@818.9,1208.66 ; R36.2@818.9,1208.66 U6.27@818.9,1271.65 R36.2@818.9,1208.66
NetR39_1: R39.1 U7.6 | length 48.5
  Bottom Layer w9.84: U7.6@1834.65,994.09 1855.32,994.09 R39.1@1875,1013.78
NetR42_1: R42.1 U6.64 | length 129.6
  Top Layer w7.87: v2(590.55,1820.87) R42.1@590.55,1859.06
  Bottom Layer w7.87: v2(590.55,1820.87) 625,1820.87 626.97,1818.9 U6.64@681.1,1818.9
NetR43_1: R43.1 U6.66 | length 52
  Bottom Layer w7.87: U6.66@755.91,1877.95 755.91,1927.17 R43.1@757.87,1929.13
NetR44_1: R44.1 U6.88 | length 150.3
  Bottom Layer w7.87: U6.88@1102.36,1877.95 1102.36,1930.25 1116.01,1943.9 R44.1@1194.69,1943.9
NetR47_1: R47.1 U6.3 | length 66.4
  Bottom Layer w7.87: R47.1@1181.1,1211.81 1196.85,1227.56 U6.3@1196.85,1271.65
NetR49_2: R49.2 U6.48 | length 93.3
  Bottom Layer w7.87: R49.2@605.32,1609.25 647.64,1566.93 U6.48@681.1,1566.93
NetR52_1: R52.1 U8.11 | length 915.6
  Top Layer w9.84: v1(1606.19,815.29) 1607.95,817.05 1607.95,1127.95 v1(1635,1155)
  Bottom Layer w7.87: R52.1@1142.91,787.4 1207.4,787.4 1234,814 1235.29,815.29 v1(1606.19,815.29)
  Bottom Layer w10: v1(1635,1155) 1655,1155 1673.23,1173.23 U8.11@1673.23,1216.54
NetR53_2: R53.2 U8.9 | length 1006.4
  Top Layer w9.84: 1652.11,912.89 v1(1691,874)
  Top Layer w10: 1652.11,912.89 1625.75,939.25 1625.75,994.46 1625.75,1013.41 1625.75,1095.75 v1(1660,1130)
  Bottom Layer w7.87: R53.2@1144.88,836.61 1596.67,836.61 1597.16,837.1 1615.23,837.1 1615.71,836.61 1665.61,836.61 1691,862 v1(1691,874)
  Bottom Layer w9.84: v1(1660,1130) 1706,1130 1724.41,1148.41 U8.9@1724.41,1216.54
NetR54_2: R54.2 R58.1 U11.3 | length 135.7
  Bottom Layer w7.87: R54.2@249.21,816.93 R58.1@249.21,846.46 R54.2@249.21,816.93 ; R54.2@249.21,816.93 259.06,807.09 ; R54.2@249.21,816.93 259.06,807.09 ; 259.06,807.09 U11.3@283.46,807.09 259.06,807.09
NetR55_2: R55.2 U10.3 U11.4 | length 321
  Bottom Layer w5.91: 408.46,807.09 U11.4@307.09,807.09 408.46,807.09 ; 408.46,807.09 414.37,801.18 ; 408.46,807.09 414.37,801.18 ; 414.37,801.18 U10.3@429.53,801.18 ; 414.37,801.18 U10.3@429.53,801.18 ; U10.3@429.53,801.18 U10.3@429.92,801.57 ; U10.3@429.53,801.18 U10.3@429.92,801.57 ; U10.3@429.92,801.57 R55.2@429.92,836.61 U10.3@429.92,801.57
NetR56_1: R56.1 Y1.3 | length 46.5
  Bottom Layer w7.87: R56.1@1338.58,1345.28 1338.58,1313.98 Y1.3@1342.36,1299.21
NetR57_2: R57.2 Y1.1 | length 55.1
  Bottom Layer w9.84: Y1.1@1393.54,1259.84 1411.42,1259.84 R57.2@1448.62,1259.84
NetR61_1: R61.1 U13.12 | length 57.8
  Top Layer w7.87: U13.12@1360.24,2484.25 1381.89,2484.25 R61.1@1407.48,2509.84
NetR62_1: R62.1 U13.11 | length 50.5
  Top Layer w7.87: U13.11@1360.24,2468.5 1399.61,2468.5 R62.1@1407.48,2460.63
NetR63_1: R63.1 U13.10 | length 70.7
  Top Layer w7.87: U13.10@1360.24,2452.76 1376.97,2452.76 1392.72,2437.01 1392.72,2426.18 R63.1@1407.48,2411.42
NetR66_1: R66.1 U15.34 | length 55.1
  Top Layer w9.84: R66.1@757.87,2632.87 U15.34@757.87,2687.99
NetR73_1: R73.1 U21.2 | length 118.3
  Bottom Layer w9.84: R73.1@1208.66,2854.33 1218.5,2844.49 U21.2@1322.83,2844.49
NetR74_1: R74.1 U21.3 | length 94
  Bottom Layer w9.84: R74.1@1279.53,2925.2 1279.53,2881.89 1297.24,2864.17 U21.3@1322.83,2864.17
NetR75_1: R75.1 U21.5 | length 224.1
  Top Layer w9.84: R75.1@1279.53,2736.22 1279.53,2869.09 v2(1323.82,2913.39)
  Bottom Layer w7.87: v2(1323.82,2913.39) 1348.43,2913.39 U21.5@1348.43,2909.45
NetR76_1: R76.1 U21.7 | length 107.3
  Bottom Layer w10: U21.7@1387.8,2909.45 R76.1@1387.8,3016.73
NetR77_1: R77.1 U21.8 | length 179.2
  Bottom Layer w9.84: U21.8@1407.48,2909.45 1407.48,2918.31 1446.85,2957.68 1446.85,3000 R77.1@1498.03,3051.18
NetR78_1: R78.1 U21.9 | length 109.6
  Bottom Layer w9.84: U21.9@1433.07,2883.86 1456.69,2883.86 1496.06,2923.23 1496.06,2950.79 R78.1@1498.03,2952.76
NetR79_1: R79.1 U21.1 | length 71.1
  Bottom Layer w7.87: R79.1@1259.84,2805.12 1279.53,2824.8 U21.1@1322.83,2824.8
NetR80_1: R80.1 U21.10 | length 65
  Bottom Layer w9.84: U21.10@1433.07,2864.17 R80.1@1498.03,2864.17
NetU13_1: U13.1 U16.5 | length 576.4
  Top Layer w7.87: v2(1058.07,2091.54) 1107.39,2140.85 1107.39,2239.28 1181.1,2312.99 1181.1,2445.87 1219.49,2484.25 U13.1@1299.21,2484.25
  Bottom Layer w9.84: U16.5@1022.64,2087.6 1026.57,2091.54 v2(1058.07,2091.54)
NetU13_2: U13.2 U17.5 | length 492.8
  Top Layer w7.87: U13.2@1297.24,2468.5 1315.94,2468.5 v1(1328.74,2455.71)
  Copper Layer 3 w7.87: v2(1254.92,2091.54) 1254.92,2239.17 v1(1328.74,2312.99)
  Bottom Layer w7.87: v1(1328.74,2312.99) 1357.99,2342.24 1357.99,2426.46 v1(1328.74,2455.71)
  Bottom Layer w9.84: U17.5@1219.49,2087.6 1223.43,2091.54 v2(1254.92,2091.54)
NetU13_3: U13.3 U19.5 | length 758.4
  Top Layer w7.87: v2(861.22,2091.54) 915.35,2145.67 1020.67,2145.67 1058.07,2183.07 1058.07,2386.81 v1(1131.89,2460.63) ; v1(1230.39,2440.94) 1247.05,2440.94 1258.86,2452.76 U13.3@1297.24,2452.76
  Bottom Layer w7.87: v1(1131.89,2460.63) 1210.71,2460.63 v1(1230.39,2440.94)
  Bottom Layer w9.84: U19.5@825.79,2087.6 829.72,2091.54 v2(861.22,2091.54)
NetU13_9: U13.9 U20.5 | length 453
  Top Layer w7.87: U13.9@1360.24,2437.01 1368.11,2437.01 1373.03,2432.09 1373.03,2317.91 1525.59,2165.35 v1(1614.17,2165.35)
  Bottom Layer w9.84: v1(1614.17,2165.35) U20.5@1614.17,2185.04
OUT_A+: C14.2 J1.2 L1.1 U1.19
OUT_A-: C16.2 J1.1 L2.1 U1.23
OUT_B+: C18.2 J7.2 L3.1 U1.30 | length 41
  Top Layer w10: C18.2@3650,1984 3650,2025
OUT_B-: C20.2 J7.1 L4.1 U1.26
PG: R16.2 U2.11 | length 291.6
  Top Layer w9.84: R16.2@2595.72,4665.65 v1(2624.66,4665.65) ; v1@2629.19,4456.56 2639.03,4446.71 U2.11@2639.03,4410.3
  Copper Layer 3 w9.84: v1(2624.66,4665.65) 2624.66,4463.91 2630.17,4458.4 v1(2630.17,4455.65)
PVDD-EXT: J17.1 J18.1
  other v1: 2962.5,3563.62 2997.5,3563.62 3037.5,3563.62 3072.5,3563.62 2937.5,3595 3097.5,3595 2937.5,3640 3097.5,3640 2937.5,3685 3097.5,3685 2962.5,3710 2997.5,3710 3037.5,3710 3072.5,3710
PVDD_5828: C2.2 C3.2 C4.1 C5.1 C6.2 C7.2 C8.1 C9.1 J14.2 J18.2 U1.17 U1.18 U1.31 U1.32 | length 570.7
  Bottom Layer w9.84: C9.1@3321.42,1372.07 3329.37,1380.02 C7.2@3458.56,1380.02 3458.02,1380.56 3458.02,1427.8 C6.2@3458.02,1459.05 3471.3,1472.33 C5.1@3471.3,1519.19 ; C8.1@3321.42,2108.19 3329.37,2100.24 C2.2@3458.56,2100.24 3458.02,2099.7 C3.2@3458.02,2021.2 3471.3,2007.93 C4.1@3471.3,1961.07
  other v1: 3256.81,1305.26 3299.81,1305.26 3347,1305.26 3390,1305.26 3227.5,1345.77 3423.04,1358.32 3227.5,1398.36 3423.04,1401.32 3422.5,1437.36 3256.81,1438.87 3299.81,1438.87 3347,1438.87 3390,1438.87 3422.5,1480.36 3439.5,1518.36 3439.5,1961.9 3422.5,1999.9 3256.81,2041.38 3299.81,2041.38 3347,2041.38 3390,2041.38 3422.5,2042.9 3423.04,2078.93 3227.5,2081.9 3423.04,2121.93 3227.5,2134.48 3256.81,2175 3299.81,2175 3347,2175 3390,2175 2967.5,3245.16 3004.17,3245.16 3040.83,3245.16 3077.5,3245.16 2967.5,3275.16 3004.17,3275.16 3040.83,3275.16 3077.5,3275.16 2967.5,3305.16 3004.17,3305.16 3040.83,3305.16 3077.5,3305.16 2967.5,3335.16 3004.17,3335.16 3040.83,3335.16 3077.5,3335.16
Q1-D: D1.1 D1.2 L5.2 Q1.5 Q1.6 Q1.7 Q1.8
Q1-G: Q1.4 R15.2 | length 280
  Top Layer w27.56: Q1.4@2349.23,4222.31 2461.82,4222.3 R15.2@2629.19,4222.3
Q1-S: Q1.1 Q1.2 Q1.3 R18.2 R21.2 | length 386.1
  Top Layer w9.84: v1(2781.75,4057.93) R18.2@2781.75,4099.27
  Top Layer w20: R21.2@2458.79,4110.65 v1(2530.17,4110.65)
  Copper Layer 3 w9.84: v1(2530.17,4110.65) 2729.03,4110.65 v1(2781.75,4057.93)
Right+: C13.2 J6.1 L3.2
Right-: C21.2 J6.2 L4.2
RT: R20.1 U2.10 | length 86.8
  Top Layer w9.84: R20.1@2648.87,4492.97 2658.71,4483.13 U2.10@2658.71,4410.3
SCL: R37.2 U6.37 U7.8 U15.25 | length 7886
  Top Layer w10: v5@62.72,2615 v5(65,2615) 346.73,2615 419.72,2687.99 U15.25@580.71,2687.99 ; v5(505,3675) 525,3675 705,3495 1120,3495 1501,3114 ; v1(861.22,811) 861.22,622.78 882,602 v1(882,600.39)
  Bottom Layer w7.87: 620.08,1377.95 635.83,1393.7 U6.37@681.1,1393.7
  Bottom Layer w9.84: 620.08,1377.95 620.08,1245.08 861.22,1003.94 v1(861.22,811) ; v1(882,600.39) 1327.39,600.39 1405,678 1684.81,678 1702.76,695.95 R37.2@1702.76,720.06 ; 1756.06,720.06 1834.65,798.65 ; R37.2@1702.76,720.06 1703,720.31 R37.2@1702.76,720.55 R37.2@1702.76,720.06
  Bottom Layer w10: 199.09,1755.97 90,1865.06 90,2545 65,2570 v5(65,2615) 87.13,2637.13 87.13,2686.64 125,2724.51 125,3105 289.21,3269.21 289.21,3564.21 400,3675 v5(505,3675) ; 200,1755 225,1730 225,1108.66 418.66,915 551.54,915 620,846.54 620,779.53 547.5,707.03 547.5,668.05 598.05,617.5 802.5,617.5 819.61,600.39 v1(882,600.39) ; R37.2@1702.76,720.06 1756.06,720.06 ; 1834.65,798.65 U7.8@1834.65,954.72
SCL_XMOS: J22.2 TP13.1 U7.5 U8.12 U21.12 | length 4340.7
  Top Layer w10: J22.2@1413,272 1350,335 1350,574.72 1425.28,650 1645,650 1725,730 v1(1725,748)
  Bottom Layer w10: TP13.1@600.39,450 630.39,420 830,420 855,395 855,340.86 870.86,325 1360,325 J22.2@1413,272 ; U21.12@1433.07,2824.8 1464.57,2824.8 1501,2788.37 1501,2675.62 1477.5,2652.12 1477.5,2415 1580,2312.5 1676,2312.5 1676,1976.87 1817.5,1835.37 1817.5,1266 ; U8.12@1647.64,1216.54 1647.64,1256.52 1671.12,1280 1803.5,1280 1817.5,1266 ; v1(1725,748) 1777,800 1777,983 1807.78,1013.78 U7.5@1834.65,1013.78 1850,1029.13 1850,1233.5 1817.5,1266
SCLK: J27.2 TP16.1 U1.8 | length 2507.4
  Top Layer w9.84: TP16.1@2135.5,2591.24 1955.67,2411.4 1955.67,1799.33 1987.8,1767.2 2049.13,1767.2 2071.34,1745 2642.08,1745 ; 2642.5,1745 2947.08,1745 2955,1752.92 U1.8@3153.72,1752.92
  Bottom Layer w10: J27.2@1771.65,2559.06 1852.6,2640 2086.74,2640 TP16.1@2135.5,2591.24
SCLK-MUX: J27.1 R61.2 | length 245.2
  Top Layer w9.84: R61.2@1446.85,2509.84 1496.06,2559.06 J27.1@1671.65,2559.06
SCLK-SPDIF: C102.1 R60.2 U16.1 | length 275.6
  Top Layer w9.84: C102.1@826.77,2391.73 v2(861.22,2391.73)
  Bottom Layer w9.84: R60.2@826.77,2391.73 900.59,2391.73 945.87,2346.46 U16.1@945.87,2243.11
SDA: R38.2 U6.38 U7.1 U15.24 | length 7573.4
  Top Layer w10: v5(120,2685) 217.02,2685 224.86,2677.17 319.17,2677.17 388.07,2746.06 U15.24@522.64,2746.06 ; v5(505,3628.22) 505,3620 650,3475 654.7,3475 654.78,3475.07 673.73,3475.07 673.8,3475 1112.17,3475 1476.38,3110.79 ; v1(804,863) 826,841 927,841 1069,699 v1(1284,699)
  Bottom Layer w7.87: 604.39,1409.39 604.33,1409.45 U6.38@681.1,1409.45
  Bottom Layer w9.84: 604.39,1409.39 596,1401 596,1223 804,1015 v1(804,863) ; 1679.87,787.87 1730.47,838.47 1730.47,946.41 1722.22,954.66 U7.1@1708.66,954.72 U7.1@1708.66,954.72
  Bottom Layer w10: v5(120,2685) 120,2684.14 110,2674.14 110,1872.35 245,1737.35 245,1113.94 426.07,932.87 558.94,932.87 728.94,762.87 932.8,762.87 996.67,699 v1(1284,699) 1306,721 1544.83,721 R38.2@1545.28,720.55 1545.28,755.28 1577.87,787.87 1679.87,787.87 ; v5@120,2687.17 140.83,2707.99 192.42,2707.99 225,2740.57 225,3083.04 239.34,3097.39 239.34,3187.65 307.09,3255.39 307.09,3527.09 408.22,3628.22 v5(505,3628.22)
SDA_XMOS: J23.2 TP14.1 U7.4 U8.13 U21.13 | length 3856.8
  Top Layer w10: J23.2@1195,275 1275,355 1275,380 1330,435 1330,580 1501.35,751.35 1584.65,751.35 v1(1582,754)
  Copper Layer 3 w10: v5(1500,2340) 1500,2140.14 v5(1640,2000.14)
  Bottom Layer w10: TP14.1@600.39,250 625.39,275 J23.2@1195,275 ; U21.13@1407.48,2799.21 1450.63,2799.21 1461.69,2788.15 1461.69,2671.69 1455,2665 1455,2385 v5(1500,2340) ; v1(1582,754) 1691.65,754 1755,817.35 1755,999 1740.22,1013.78 U7.4@1708.66,1013.78 1601,1121.44 1601,1161.9 1622.05,1182.95 U8.13@1622.05,1216.54 1622.05,1282.05 1662.5,1322.5 1701.21,1322.5 1799.63,1420.91 1799.63,1754.77 1640,1914.4 v5(1640,2000.14)
SDIN: J29.2 TP18.1 U1.7 | length 2274.8
  Top Layer w10: TP18.1@2135.5,2394.81 1978.22,2237.52 1978.22,1809.38 2002.6,1785 2065,1785 2085,1765 2630.17,1765 2630.36,1765 2935.36,1765 2948.87,1778.51 U1.7@3153.72,1778.51
  Bottom Layer w10: J29.2@1771.65,2362.2 1861.45,2452 2078.31,2452 TP18.1@2135.5,2394.81
SDIN-MUX: J29.1 R63.2 | length 245.2
  Top Layer w9.84: R63.2@1446.85,2411.42 1495.47,2362.8 1509.44,2362.8 1510.03,2362.2 J29.1@1671.65,2362.2
SDIN-SPDIF: J31.3 R64.2 | length 76.4
  Bottom Layer w9.84: R64.2@1525.59,2044.29 1527.17,2042.72 J31.3@1527.17,1968.5
SDIN-XMOS: J31.1 R44.2 | length 120.6
  Bottom Layer w9.84: R44.2@1216.73,1943.9 1302.56,1943.9 J31.1@1327.17,1968.5
SDOUT-MUX: J31.2 U13.4 | length 567.2
  Top Layer w7.87: U13.4@1297.24,2437.01 1280.51,2437.01 1254.92,2411.42 1254.92,2288.39 1427.17,2116.14 J31.2@1427.17,1968.5
SDOUT-SEL: R72.2 R75.2 U20.6 | length 683.7
  Top Layer w9.84: R75.2@1279.53,2679.13 1281.5,2677.17 v1(1318.9,2677.17)
  Bottom Layer w9.84: v1(1318.9,2677.17) 1427.17,2568.9 1427.17,2312.99 1538.58,2201.57 R72.2@1574.8,2201.57 1577.95,2204.72 U20.6@1614.17,2204.72
SDOUT-SPDIF: C107.1 R67.2 U19.1 | length 226.9
  Top Layer w9.84: v2(738.19,2347.44) C107.1@738.19,2391.73
  Bottom Layer w9.84: R67.2@664.37,2347.44 v2(738.19,2347.44) 738.19,2298.23 749.02,2287.4 U19.1@749.02,2243.11
SPDIF-BCK: R60.1 U15.8 U15.19 | length 866.3
  Top Layer w9.84: U15.19@522.64,2844.49 v2(600.39,2844.49) 629.92,2844.49 659.45,2874.02 U15.8@659.45,3020.67
  Bottom Layer w9.84: v2(600.39,2844.49) 600.39,2549.21 688.98,2460.63 797.24,2460.63 R60.1@826.77,2431.1
SPDIF-DIN: R64.1 U15.10 | length 1661.9
  Top Layer w9.84: v2(605.32,2967.52) 620.08,2982.28 U15.10@620.08,3020.67
  Bottom Layer w9.84: v2(605.32,2967.52) 664.37,3026.57 861.22,3026.57 984.25,2903.54 984.25,2534.45 1156.5,2362.2 1230.32,2362.2 1279.53,2312.99 1279.53,2214.57 1394.68,2099.41 R64.1@1525.59,2099.41
SPDIF-DOUT: R67.1 U15.17 | length 694.4
  Top Layer w9.84: v2(442.91,2854.33) 472.44,2883.86 U15.17@522.64,2883.86
  Bottom Layer w9.84: v2(442.91,2854.33) 427,2838.42 427,2573 613.19,2386.81 R67.1@664.37,2386.81
SPDIF-FSYNC: R65.1 U15.9 U15.18 | length 778.9
  Top Layer w9.84: U15.18@522.64,2864.17 561.02,2864.17 570.87,2874.02 570.87,2898.62 585.63,2913.39 v2(620.08,2913.39) 639.76,2933.07 U15.9@639.76,3020.67
  Bottom Layer w9.84: v2(620.08,2913.39) 664.37,2869.09 664.37,2583.66 738.19,2509.84 R65.1@816.93,2509.84
SPDIF-IN: U14.3 U15.33 | length 707.8
  Top Layer w9.84: U14.3@282.28,2262.2 441.34,2262.2 688.98,2509.84 688.98,2608.27 738.19,2657.48 U15.33@738.19,2687.99
SPDIF-MCLK: TP15.1 U15.7 U15.20 | length 495.8
  Top Layer w9.84: U15.20@522.64,2824.8 570.87,2824.8 610.24,2785.43 669.29,2785.43 713.58,2829.72 713.58,2947.83 679.13,2982.28 U15.7@679.13,3020.67 TP15.1@679.13,3085.63
SPDIF-OUT: U12.3 U15.15 | length 255.2
  Top Layer w9.84: U12.3@280.32,2954.33 441.34,2954.33 472.44,2923.23 U15.15@522.64,2923.23
SS: C37.2 U2.9 | length 90.8
  Top Layer w9.84: U2.9@2678.4,4410.3 2678.4,4473.29 C37.2@2698.08,4492.97
SW: L6.1 U4.3
USB_D_M: J25.2 U6.47 | length 532.2
  Top Layer w9.84: J25.2@169.29,1600.39 564.96,1600.39 v2(590.55,1574.8)
  Bottom Layer w7.87: v2(590.55,1574.8) 614.17,1551.18 U6.47@681.1,1551.18
USB_D_P: J25.3 U6.46 | length 528.1
  Top Layer w7.87: J25.3@169.29,1574.8 241.14,1574.8 265.75,1550.2 v2(541.34,1550.2)
  Bottom Layer w7.87: v2(541.34,1550.2) 575.79,1550.2 590.55,1535.43 U6.46@681.1,1535.43
USB_ID: J25.4 U6.43 | length 547.7
  Top Layer w7.87: J25.4@169.29,1549.21 212.6,1549.21 285.43,1476.38 286.06,1477 287.06,1476 v2(598,1476)
  Bottom Layer w7.87: v2(598,1476) 629.54,1476 641.73,1488.19 U6.43@681.1,1488.19
UVLO: R14.2 U2.12 | length 90.8
  Top Layer w9.84: R14.2@2599.66,4492.97 2599.66,4451.64 2619.34,4431.95 U2.12@2619.34,4410.3
VBUS-XMOS: C83.1 R46.1 U6.45 | length 162.6
  Bottom Layer w7.87: R46.1@566.93,1464.57 566.93,1504.92 C83.1@565.94,1505.91 579.72,1519.68 U6.45@681.1,1519.68
VBUS_IN: C87.2 J25.1 L7.1 R46.2 R59.2 | length 503.4
  Copper Layer 3 w19.68: v1(275.59,1628.94) 275.59,1471.46 319.88,1427.17 v2(492.13,1427.17)
  Bottom Layer w9.84: R46.2@564.96,1427.17 R46.2@566.93,1425.2 R59.2@566.93,1389.76
  Bottom Layer w19.68: v2(492.13,1427.17) R46.2@564.96,1427.17
VIN: C23.1 C24.1 C25.1 C26.1 C27.1 J12.1 R12.1 TP6.1
  other v1: 1640,4310.55 1640,4351.41 1640,4392.27 1640,4433.13 1640,4473.99 1884.34,4500 1640,4514.85 1841.92,4517.57 1926.77,4517.57 1640,4555.71 1824.34,4560 1944.34,4560 1640,4596.56 1841.92,4602.43 1926.77,4602.43 1884.34,4620 1640,4637.42 1640,4678.28 1640,4719.14
VINL: C109.1 U15.47 | length 591.7
  Top Layer w9.84: v1(639.76,3188.98) 831.69,3188.98 900.59,3120.08 900.59,2957.68 885.83,2942.91 U15.47@855.32,2942.91
  Bottom Layer w9.84: C109.1@551.18,3188.98 v1(639.76,3188.98)
VINR: C108.1 U15.48 | length 722.1
  Top Layer w9.84: U15.48@855.32,2962.6 v1(855.32,3100.39)
  Bottom Layer w9.84: C108.1@551.18,3503.94 551.18,3311 610.49,3251.69 704.02,3251.69 v1(855.32,3100.39)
